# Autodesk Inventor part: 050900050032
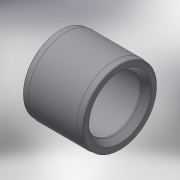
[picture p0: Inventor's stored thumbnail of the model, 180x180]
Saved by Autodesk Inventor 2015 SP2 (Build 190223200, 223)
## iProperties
Created: 2017-11
Part Number: 050900050032
Material: Generic
Description: PLASSON BUSHING-CEMENT PVC 50-32
Document SubType Name: Modeling
Designer: KIM
Density: 1 g/cm^3
Appearance: Default
Author: KIM
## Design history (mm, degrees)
derived "050900.ipt"
feature "Solid1::050900.ipt"
tag "TaggingFeature1"
body "Solid1"
other parameters: "d0" = 32, "d2" = 22, "d3" = 31, "d7" = 3.1, "d11" = 3.1, "d12" = 0.5, "d14" = 0.5, "d15" = 3.1, "d17" = 0.5, "d18" = 0.5, "d19" = 28.48, "d20" = 1.8, "d21" = 6.456, "d_" = 32, "L_" = 31, "l_" = 22, "z_" = 2
